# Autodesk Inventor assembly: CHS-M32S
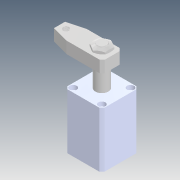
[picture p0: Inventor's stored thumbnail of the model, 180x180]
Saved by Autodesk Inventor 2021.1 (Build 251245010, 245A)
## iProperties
Created: 2020-02
Part Number: CHS-M32S
Description: STEP AP214
Document SubType Name: Assembly
Designer: user
Title: chs-m32s_asm.STEP
Revision Number: ÈÎºÎ
Sending System: SolidWorks 2016
Preprocessor: SwSTEP 2.0
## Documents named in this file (5)
- D:\Vault_2016\Projekty\Clamptek\Hydraulic\CHS\CHS-32\Inventor\CHS-M32S\CHS-M32S.iam
- D:\Vault_2016\Projekty\Clamptek\Hydraulic\CHS\CHS-32\Inventor\CHS-M32S\CHS-32S-02_4_1.ipt
- D:\Vault_2016\Projekty\Clamptek\Hydraulic\CHS\CHS-32\Inventor\CHS-M32S\CHS-32S-01_5.ipt
- D:\Vault_2016\Projekty\Clamptek\Hydraulic\CHS\CHS-32\Inventor\CHS-M32S\M16_5.ipt
- D:\Vault_2016\Projekty\Clamptek\Hydraulic\CHS\CHS-32\Inventor\CHS-M32S\CHS-M32BT.ipt
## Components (4 placed, 4 different names)
1. CHS-32S-02_4_1_1
2. CHS-32S-01_5_2
3. M16_5_3
4. CHS-M32BT_4
